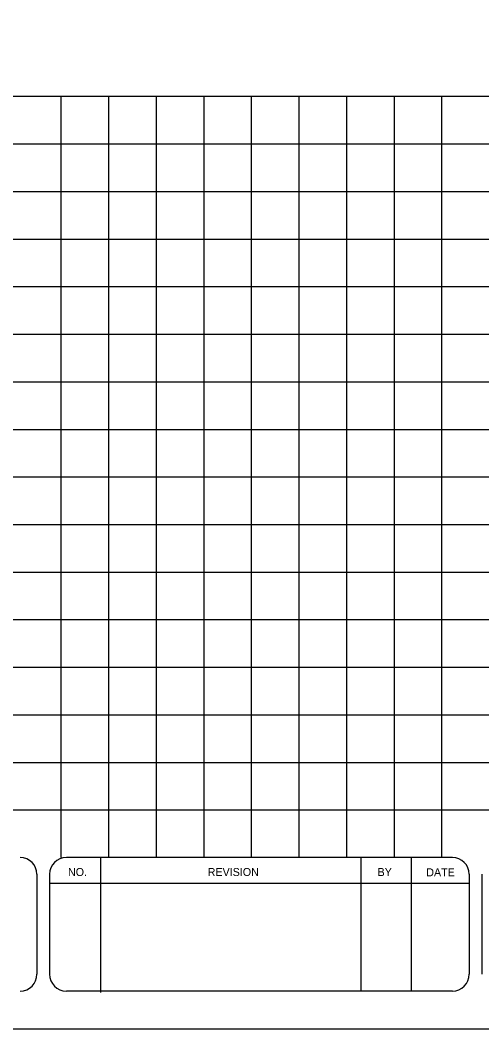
# Model space of a CAD drawing. Extents: x -4 to 16, y -3 to 9.7.
# Drawn here: x 6.24 to 8.66, y -0.9 to 4.4 of the extents above; entities that cross this region are included whole.
import ezdxf

# ---------------------------------------------------------------- set-up
doc = ezdxf.new("R2010")
doc.units = 0
for name, color, linetype in [('Baseline Bearing and Curve Data', 7, 'Continuous'), ('Baseline Station and Tick Mark', 7, 'Continuous'), ('Centerline (Construction)', 7, 'Continuous'), ('Default', 7, 'Continuous'), ('Property Corners', 7, 'Continuous')]:
    doc.layers.add(name, color=color, linetype=linetype)

msp = doc.modelspace()

# ---------------------------------------------------------------- linework, layer by layer
at = {"layer": 'Baseline Bearing and Curve Data'}
for p, q in [((6.7, 4), (6.7, 0)), ((7.2, 4), (7.2, 0)), ((7.7, 4), (7.7, 0)), ((8.2, 4), (8.2, 0)), ((0, 3.5), (15.4, 3.5)), ((0, 3), (15.4, 3)), ((0, 2.5), (15.4, 2.5)), ((0, 2), (15.4, 2)), ((0, 1.5), (15.4, 1.5)), ((0, 1), (15.4, 1)), ((0, 0.5), (15.4, 0.5))]:
    msp.add_line(p, q, dxfattribs=at)
at = {"layer": 'Baseline Station and Tick Mark'}
msp.add_line((0, 4), (15.4, 4), dxfattribs=at)
at = {"layer": 'Centerline (Construction)'}
msp.add_lwpolyline([(-0.55, -0.9), (15.95, -0.9), (15.95, 9.7), (-0.55, 9.7)], close=True, dxfattribs=at)
at = {"layer": 'Default'}
for p, q in [((8.5071, 0), (6.4781, 0)), ((6.6581, -0.0035), (6.6581, -0.7093)), ((8.0253, -0.0035), (8.0253, -0.7005)), ((8.29, -0.0035), (8.29, -0.7005)), ((6.3237, -0.0882), (6.3237, -0.6131)), ((6.3899, -0.0882), (6.3899, -0.6131)), ((8.5953, -0.0882), (8.5953, -0.6131)), ((8.6615, -0.0882), (8.6615, -0.6131)), ((8.5988, -0.1359), (6.3934, -0.1359)), ((8.5071, -0.7014), (6.4781, -0.7014))]:
    msp.add_line(p, q, dxfattribs=at)
for centre, major_axis, start_param, end_param in [((6.2355, -0.0882), (0, 0.0882), 4.712389, 6.283185), ((6.4781, -0.0882), (0, 0.0882), 0, 1.570796), ((8.5071, -0.0882), (0, 0.0882), 4.712389, 6.283185), ((6.2355, -0.6131), (0, 0.0882), 3.141593, 4.712389), ((6.4781, -0.6131), (0, -0.0882), 4.712389, 6.283185), ((8.5071, -0.6131), (0, 0.0882), 3.141593, 4.712389)]:
    msp.add_ellipse(centre, major_axis=major_axis, ratio=0.999927, start_param=start_param, end_param=end_param, dxfattribs=at)
at = {"layer": 'Property Corners'}
for p, q in [((6.45, 4), (6.45, 0)), ((6.95, 4), (6.95, 0)), ((7.45, 4), (7.45, 0)), ((7.95, 4), (7.95, 0)), ((8.45, 4), (8.45, 0)), ((0.7, 3.75), (14.7, 3.75)), ((0.7, 3.25), (14.7, 3.25)), ((0.7, 2.75), (14.7, 2.75)), ((0.7, 2.25), (14.7, 2.25)), ((0.7, 1.75), (14.7, 1.75)), ((0.7, 1.25), (14.7, 1.25)), ((0.7, 0.75), (14.7, 0.75)), ((0.7, 0.25), (14.7, 0.25))]:
    msp.add_line(p, q, dxfattribs=at)

# ---------------------------------------------------------------- texts
at = {"layer": 'Default'}
for s, p in [('NO.', (6.4869, -0.097)), ('REVISION', (7.2209, -0.097)), ('BY', (8.1136, -0.097)), ('DATE', (8.3694, -0.0987))]:
    msp.add_text(s, height=0.04207, dxfattribs=at).set_placement(p)

doc.saveas('drawing.dxf')
